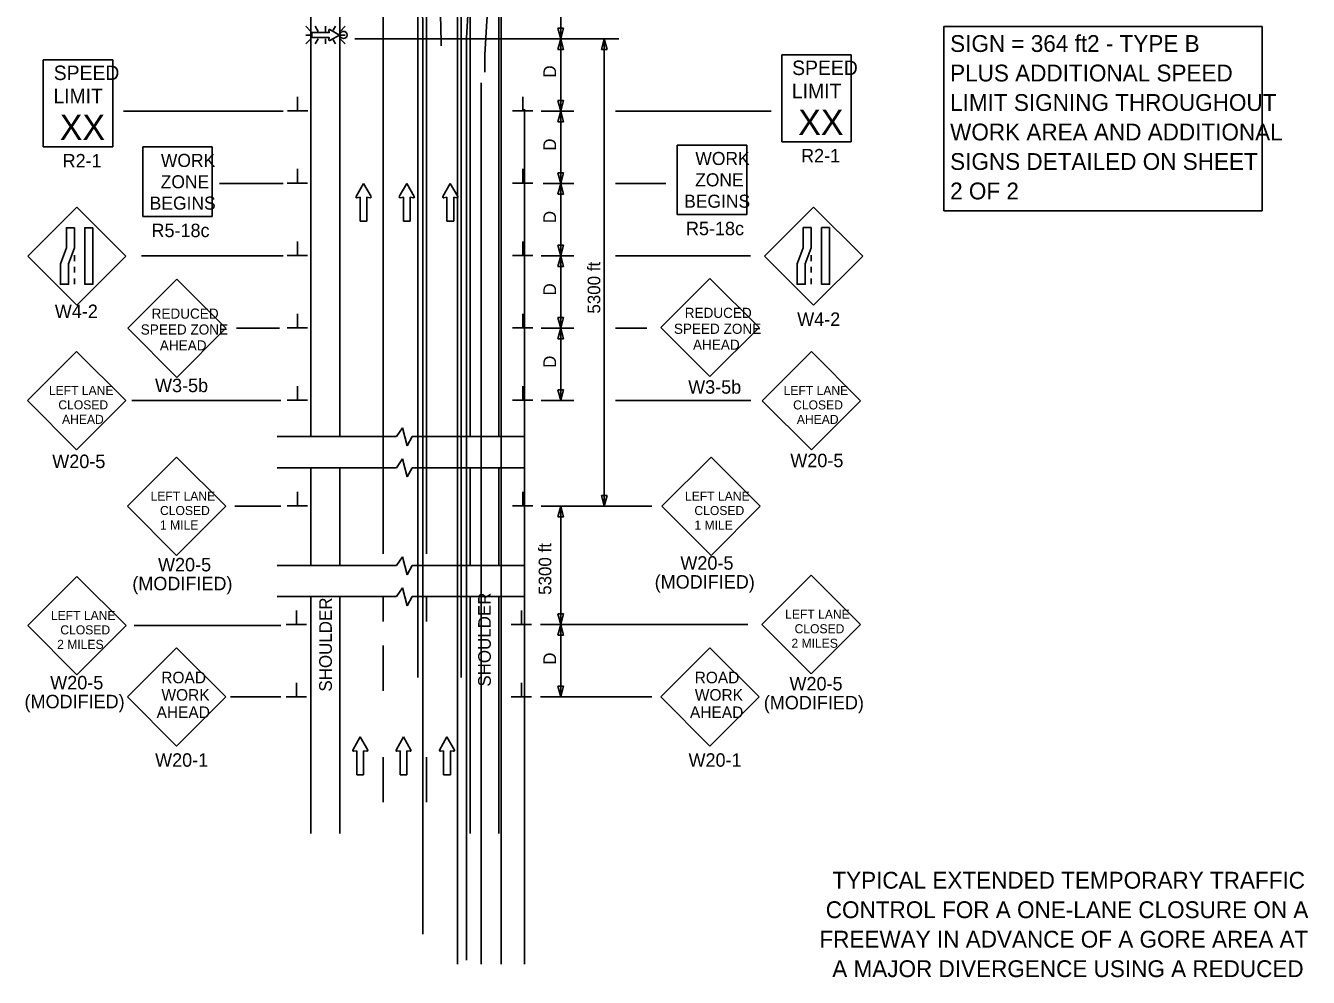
# Model space of a CAD drawing. Extents: x 16284 to 18465, y 5417 to 6974.
# Drawn here: x 16728 to 17436, y 5990 to 6516 of the extents above; entities that cross this region are included whole.
import ezdxf

# ---------------------------------------------------------------- set-up
doc = ezdxf.new("R2010")
doc.units = 0
for name, color, linetype in [('ALI_LEGAL_EX', 7, 'Continuous'), ('BORDER', 7, 'Continuous'), ('MT_SCRATCH_LEVEL_E', 7, 'Continuous'), ('PAVT_EDGE_EX', 7, 'Continuous'), ('TRAFFIC_SIGNS_PR', 7, 'Continuous'), ('TYPICAL_TEXT_DIMEN_EX', 7, 'Continuous'), ('TYPICAL_TEXT_DIMEN_PR', 7, 'Continuous')]:
    doc.layers.add(name, color=color, linetype=linetype)

msp = doc.modelspace()

# ---------------------------------------------------------------- linework, layer by layer
at = {"layer": 'ALI_LEGAL_EX'}
for p, q in [((16944.3, 6974.12), (16944.3, 6155.98)), ((16968.3, 6974.12), (16968.3, 6155.98)), ((16966.29, 6836.53), (16966.29, 5997.6)), ((16990.29, 6836.53), (16990.29, 5997.6)), ((16925.13, 6287.02), (16925.13, 6564.7)), ((16949.13, 6287.02), (16949.13, 6564.7)), ((16947.12, 6014.17), (16947.12, 6514.52)), ((16971.12, 5999.68), (16971.12, 6500.03)), ((16979.26, 5997.6), (16979.26, 6484.64)), ((17003.26, 5997.6), (17003.26, 6470.15)), ((16925.13, 6301.47), (16925.13, 6224.31)), ((16949.13, 6301.47), (16949.13, 6224.31))]:
    msp.add_line(p, q, dxfattribs=at)
for points in [[(16925.13, 6487.02), (16925.13, 6509.03)], [(16949.13, 6487.02), (16949.13, 6509.03)], [(16925.13, 6387.02), (16925.13, 6412.02)], [(16949.13, 6387.02), (16949.13, 6412.02)], [(16925.13, 6312.02), (16925.13, 6287.02)], [(16925.13, 6312.02), (16925.13, 6289.11)], [(16949.13, 6289.11), (16949.13, 6312.02)], [(16925.13, 6273.62), (16925.13, 6248.62)], [(16925.13, 6200.69), (16925.13, 6187.02)], [(16949.13, 6187.02), (16949.13, 6200.69)], [(16925.13, 6173.62), (16925.13, 6148.62)], [(16925.13, 6112.02), (16925.13, 6087.02)], [(16949.13, 6087.02), (16949.13, 6112.02)]]:
    msp.add_lwpolyline(points, dxfattribs=at)
for centre, radius, start, end in [((16583.12, 6514.52), 364, 0, 57.29578), ((16593.27, 6505.1), 364, 0, 57.29578), ((17311.12, 6500.03), 340, 129.56655, 180), ((17321.27, 6490.61), 340, 129.56655, 180)]:
    msp.add_arc(centre, radius, start, end, dxfattribs=at)
at = {"layer": 'MT_SCRATCH_LEVEL_E'}
for p, q in [((16914.27, 6429.09), (16910.15, 6421.85)), ((16918.41, 6421.85), (16914.27, 6429.09)), ((16938.17, 6429.09), (16934.06, 6421.85)), ((16942.32, 6421.85), (16938.17, 6429.09)), ((16962.22, 6429.09), (16958.11, 6421.85)), ((16966.37, 6421.85), (16962.22, 6429.09)), ((16910.64, 6421.16), (16912.41, 6421.48)), ((16912.41, 6421.48), (16912.41, 6408.22)), ((16916.16, 6408.22), (16916.16, 6421.48)), ((16916.16, 6421.48), (16917.93, 6421.16)), ((16934.54, 6421.16), (16936.32, 6421.48)), ((16936.32, 6421.48), (16936.32, 6408.22)), ((16940.06, 6408.22), (16940.06, 6421.48)), ((16940.06, 6421.48), (16941.84, 6421.16)), ((16958.59, 6421.16), (16960.37, 6421.48)), ((16960.37, 6421.48), (16960.37, 6408.22)), ((16964.11, 6408.22), (16964.11, 6421.48)), ((16964.11, 6421.48), (16965.89, 6421.16)), ((16912.41, 6408.22), (16916.16, 6408.22)), ((16936.32, 6408.22), (16940.06, 6408.22)), ((16960.37, 6408.22), (16964.11, 6408.22)), ((16912.44, 6123.16), (16908.32, 6115.92)), ((16916.58, 6115.92), (16912.44, 6123.16)), ((16936.34, 6123.16), (16932.23, 6115.92)), ((16940.49, 6115.92), (16936.34, 6123.16)), ((16960.39, 6123.16), (16956.28, 6115.92)), ((16964.54, 6115.92), (16960.39, 6123.16)), ((16908.81, 6115.24), (16910.58, 6115.55)), ((16910.58, 6115.55), (16910.58, 6102.29)), ((16914.33, 6102.29), (16914.33, 6115.55)), ((16914.33, 6115.55), (16916.1, 6115.24)), ((16932.71, 6115.24), (16934.49, 6115.55)), ((16934.49, 6115.55), (16934.49, 6102.29)), ((16938.23, 6102.29), (16938.23, 6115.55)), ((16938.23, 6115.55), (16940.01, 6115.24)), ((16956.76, 6115.24), (16958.54, 6115.55)), ((16958.54, 6115.55), (16958.54, 6102.29)), ((16962.28, 6102.29), (16962.28, 6115.55)), ((16962.28, 6115.55), (16964.06, 6115.24)), ((16910.58, 6102.29), (16914.33, 6102.29)), ((16934.49, 6102.29), (16938.23, 6102.29)), ((16958.54, 6102.29), (16962.28, 6102.29))]:
    msp.add_line(p, q, dxfattribs=at)
for centre, start, end in [((16910.56, 6421.62), 150.42484, 279.96381), ((16918, 6421.62), 260.03619, 29.77312), ((16934.47, 6421.62), 150.42484, 279.96381), ((16941.91, 6421.62), 260.03619, 29.77312), ((16958.52, 6421.62), 150.42484, 279.96381), ((16965.96, 6421.62), 260.03619, 29.77312), ((16908.73, 6115.69), 150.42484, 279.96381), ((16916.17, 6115.7), 260.03619, 29.77312), ((16932.64, 6115.69), 150.42484, 279.96381), ((16940.08, 6115.7), 260.03619, 29.77312), ((16956.69, 6115.69), 150.42484, 279.96381), ((16964.13, 6115.7), 260.03619, 29.77312)]:
    msp.add_arc(centre, 0.463, start, end, dxfattribs=at)
at = {"layer": 'PAVT_EDGE_EX'}
for p, q in [((16885.13, 6564.7), (16885.13, 6289.11)), ((16901.13, 6564.7), (16901.13, 6289.11)), ((16973.13, 6564.7), (16973.13, 6289.11)), ((16989.13, 6564.7), (16989.13, 6289.11)), ((16885.13, 6271.97), (16885.13, 6217.82)), ((16901.13, 6271.97), (16901.13, 6217.82)), ((16973.13, 6271.97), (16973.13, 6217.82)), ((16989.13, 6271.97), (16989.13, 6217.82)), ((16885.13, 6200.69), (16885.13, 6069.75)), ((16901.13, 6200.69), (16901.13, 6069.75)), ((16973.13, 6200.69), (16973.13, 6069.75)), ((16989.13, 6200.69), (16989.13, 6069.75))]:
    msp.add_line(p, q, dxfattribs=at)
at = {"layer": 'TRAFFIC_SIGNS_PR'}
for p, q in [((16885.2, 6513.11), (16882.38, 6515.93)), ((16887.5, 6515.93), (16889.13, 6513.11)), ((16893.29, 6513.11), (16893.29, 6515.93)), ((16898.76, 6515.93), (16897.55, 6513.83)), ((16904.19, 6515.92), (16901.37, 6513.11)), ((16885.2, 6511.07), (16882.38, 6511.07)), ((16885.2, 6509.04), (16882.38, 6506.22)), ((16889.15, 6509.04), (16887.52, 6506.22)), ((16893.29, 6509.04), (16893.29, 6506.22)), ((16897.47, 6508.41), (16898.73, 6506.22)), ((16901.37, 6511.07), (16904.19, 6511.07)), ((16904.19, 6506.22), (16901.37, 6509.04)), ((16737.29, 6497.33), (16775.69, 6497.33)), ((16737.29, 6449.33), (16737.29, 6497.33)), ((16775.69, 6449.33), (16775.69, 6497.33)), ((17145.4, 6500.11), (17183.8, 6500.11)), ((17145.4, 6452.11), (17145.4, 6500.11)), ((17183.8, 6452.11), (17183.8, 6500.11)), ((17145.4, 6452.11), (17183.8, 6452.11)), ((16737.29, 6449.33), (16775.69, 6449.33)), ((16792.29, 6410.82), (16792.29, 6449.22)), ((16792.29, 6449.22), (16830.69, 6449.22)), ((16830.69, 6410.82), (16830.69, 6449.22)), ((17087.66, 6411.89), (17087.66, 6450.29)), ((17087.66, 6450.29), (17126.06, 6450.29)), ((17126.06, 6411.89), (17126.06, 6450.29)), ((16755.84, 6416.02), (16728.69, 6388.86)), ((16782.99, 6388.86), (16755.84, 6416.02)), ((17163, 6416.04), (17135.85, 6388.89)), ((17190.15, 6388.89), (17163, 6416.04)), ((16792.29, 6410.82), (16830.69, 6410.82)), ((17087.66, 6411.89), (17126.06, 6411.89)), ((16728.69, 6388.86), (16755.84, 6361.71)), ((16754.59, 6389.36), (16754.59, 6386.16)), ((16755.84, 6361.71), (16782.99, 6388.86)), ((17135.85, 6388.89), (17163, 6361.73)), ((17161.75, 6389.38), (17161.75, 6386.18)), ((17163, 6361.73), (17190.15, 6388.89)), ((16754.59, 6382.96), (16754.59, 6379.76)), ((17161.75, 6382.98), (17161.75, 6379.78)), ((16754.59, 6376.56), (16754.59, 6373.36)), ((16811.09, 6376.17), (16783.94, 6349.02)), ((16838.25, 6349.02), (16811.09, 6376.17)), ((17105.74, 6376.58), (17078.59, 6349.43)), ((17132.9, 6349.43), (17105.74, 6376.58)), ((17161.75, 6376.58), (17161.75, 6373.38)), ((16783.94, 6349.02), (16811.09, 6321.87)), ((16811.09, 6321.87), (16838.25, 6349.02)), ((17078.59, 6349.43), (17105.74, 6322.27)), ((17105.74, 6322.27), (17132.9, 6349.43)), ((16755.68, 6336.22), (16728.49, 6309.03)), ((16782.86, 6309.03), (16755.68, 6336.22)), ((17161.77, 6336.19), (17134.58, 6309)), ((17188.95, 6309), (17161.77, 6336.19)), ((16728.49, 6309.03), (16755.68, 6281.85)), ((16755.68, 6281.85), (16782.86, 6309.03)), ((17134.58, 6309), (17161.77, 6281.81)), ((17161.77, 6281.81), (17188.95, 6309)), ((16810.96, 6277.82), (16783.77, 6250.64)), ((16838.15, 6250.64), (16810.96, 6277.82)), ((17106.33, 6277.81), (17079.14, 6250.62)), ((17133.51, 6250.62), (17106.33, 6277.81)), ((16783.77, 6250.64), (16810.96, 6223.45)), ((16810.96, 6223.45), (16838.15, 6250.64)), ((17079.14, 6250.62), (17106.33, 6223.43)), ((17106.33, 6223.43), (17133.51, 6250.62)), ((16755.88, 6211.86), (16728.69, 6184.67)), ((16783.07, 6184.67), (16755.88, 6211.86)), ((17161.68, 6212.48), (17134.49, 6185.29)), ((17188.86, 6185.29), (17161.68, 6212.48)), ((16728.69, 6184.67), (16755.88, 6157.49)), ((16755.88, 6157.49), (16783.07, 6184.67)), ((17134.49, 6185.29), (17161.68, 6158.11)), ((17161.68, 6158.11), (17188.86, 6185.29)), ((16810.94, 6172.41), (16783.79, 6145.26)), ((16838.09, 6145.26), (16810.94, 6172.41)), ((17105.72, 6172.41), (17078.56, 6145.26)), ((17132.87, 6145.26), (17105.72, 6172.41)), ((16783.79, 6145.26), (16810.94, 6118.11)), ((16810.94, 6118.11), (16838.09, 6145.26)), ((17078.56, 6145.26), (17105.72, 6118.11)), ((17105.72, 6118.11), (17132.87, 6145.26))]:
    msp.add_line(p, q, dxfattribs=at)
for points in [[(16895.11, 6513.76), (16895.34, 6512.46), (16885.62, 6512.46), (16885.62, 6509.72), (16895.34, 6509.72), (16895.11, 6508.41)], [(16895.61, 6508.06), (16900.92, 6511.07), (16895.61, 6514.11)]]:
    msp.add_lwpolyline(points, dxfattribs=at)
for points in [[(16754.59, 6404.6), (16754.59, 6393.42), (16751.25, 6384.54), (16751.25, 6373.36), (16746.75, 6373.36), (16746.75, 6384.54), (16750.1, 6393.42), (16750.1, 6404.6)], [(16764.73, 6404.6), (16764.73, 6373.36), (16760.23, 6373.36), (16760.23, 6404.6)], [(17161.75, 6404.62), (17161.75, 6393.44), (17158.41, 6384.56), (17158.41, 6373.38), (17153.91, 6373.38), (17153.91, 6384.56), (17157.26, 6393.44), (17157.26, 6404.62)], [(17171.89, 6404.62), (17171.89, 6373.38), (17167.4, 6373.38), (17167.4, 6404.62)]]:
    msp.add_lwpolyline(points, close=True, dxfattribs=at)
msp.add_circle((16903.24, 6511.12), 2, dxfattribs=at)
for centre, start, end in [((16895.45, 6513.81), 61.48329, 189.95933), ((16895.45, 6508.36), 170.73078, 298.89165)]:
    msp.add_arc(centre, 0.341, start, end, dxfattribs=at)
at = {"layer": 'TYPICAL_TEXT_DIMEN_EX'}
msp.add_lwpolyline([(17235.07, 6515.73), (17410.86, 6515.73), (17410.86, 6414), (17235.07, 6414)], close=True, dxfattribs=at)
at = {"layer": 'TYPICAL_TEXT_DIMEN_PR'}
for p, q in [((17023.24, 6541.14), (17023.24, 6509.03)), ((17023.24, 6509.03), (17021.67, 6514.9)), ((17021.67, 6514.9), (17023.24, 6514.9)), ((17023.24, 6514.9), (17024.81, 6514.9)), ((17024.81, 6514.9), (17023.24, 6509.03)), ((16909.53, 6509.03), (17055.35, 6509.03)), ((17021.67, 6503.17), (17023.24, 6509.03)), ((17023.24, 6509.03), (17023.24, 6469.03)), ((17023.24, 6509.03), (17024.81, 6503.17)), ((17045.77, 6503.17), (17047.34, 6509.03)), ((17047.34, 6509.03), (17047.34, 6250.63)), ((17047.34, 6509.03), (17048.91, 6503.17)), ((17023.24, 6503.17), (17021.67, 6503.17)), ((17024.81, 6503.17), (17023.24, 6503.17)), ((17047.34, 6503.17), (17045.77, 6503.17)), ((17048.91, 6503.17), (17047.34, 6503.17)), ((16877.81, 6469.12), (16877.81, 6476.9)), ((17002.26, 6469.12), (17002.26, 6476.9)), ((17023.24, 6469.03), (17021.67, 6474.9)), ((17021.67, 6474.9), (17023.24, 6474.9)), ((17023.24, 6474.9), (17024.81, 6474.9)), ((17024.81, 6474.9), (17023.24, 6469.03)), ((16869.89, 6469.03), (16781.59, 6469.03)), ((16883.43, 6469.12), (16872.18, 6469.12)), ((17007.88, 6469.12), (16996.63, 6469.12)), ((17030.45, 6469.03), (17012.41, 6469.03)), ((17021.67, 6463.17), (17023.24, 6469.03)), ((17023.24, 6469.03), (17023.24, 6429.03)), ((17023.24, 6469.03), (17024.81, 6463.17)), ((17139.57, 6469.03), (17053.57, 6469.03)), ((17023.24, 6463.17), (17021.67, 6463.17)), ((17024.81, 6463.17), (17023.24, 6463.17)), ((16877.69, 6429.28), (16877.69, 6437.06)), ((17002.26, 6429.28), (17002.26, 6437.06)), ((17023.24, 6429.03), (17021.67, 6434.9)), ((17021.67, 6434.9), (17023.24, 6434.9)), ((17023.24, 6434.9), (17024.81, 6434.9)), ((17024.81, 6434.9), (17023.24, 6429.03)), ((16869.89, 6429.03), (16834.72, 6429.03)), ((16883.32, 6429.28), (16872.07, 6429.28)), ((17007.88, 6429.28), (16996.63, 6429.28)), ((17030.45, 6429.03), (17013.53, 6429.03)), ((17021.67, 6423.17), (17023.24, 6429.03)), ((17023.24, 6423.17), (17021.67, 6423.17)), ((17023.24, 6429.03), (17023.24, 6389.03)), ((17023.24, 6429.03), (17024.81, 6423.17)), ((17024.81, 6423.17), (17023.24, 6423.17)), ((17081.26, 6429.03), (17053.57, 6429.03)), ((16877.69, 6389.28), (16877.69, 6397.06)), ((17002.26, 6389.28), (17002.26, 6397.06)), ((17023.24, 6389.03), (17021.67, 6394.9)), ((17021.67, 6394.9), (17023.24, 6394.9)), ((17023.24, 6394.9), (17024.81, 6394.9)), ((17024.81, 6394.9), (17023.24, 6389.03)), ((16869.89, 6389.03), (16791.54, 6389.03)), ((16883.32, 6389.28), (16872.07, 6389.28)), ((17007.88, 6389.28), (16996.63, 6389.28)), ((17030.45, 6389.03), (17012.41, 6389.03)), ((17021.67, 6383.17), (17023.24, 6389.03)), ((17023.24, 6389.03), (17023.24, 6349.03)), ((17023.24, 6389.03), (17024.81, 6383.17)), ((17128.19, 6389.03), (17053.57, 6389.03)), ((17023.24, 6383.17), (17021.67, 6383.17)), ((17024.81, 6383.17), (17023.24, 6383.17)), ((16877.69, 6349.28), (16877.69, 6357.06)), ((17002.26, 6349.28), (17002.26, 6357.06)), ((17023.24, 6349.03), (17021.67, 6354.9)), ((17021.67, 6354.9), (17023.24, 6354.9)), ((17023.24, 6354.9), (17024.81, 6354.9)), ((17024.81, 6354.9), (17023.24, 6349.03)), ((16867.76, 6349.03), (16844.09, 6349.03)), ((16883.32, 6349.28), (16872.07, 6349.28)), ((17007.88, 6349.28), (16996.63, 6349.28)), ((17030.45, 6349.03), (17012.41, 6349.03)), ((17021.67, 6343.17), (17023.24, 6349.03)), ((17023.24, 6349.03), (17023.24, 6309.03)), ((17023.24, 6349.03), (17024.81, 6343.17)), ((17070.76, 6349.03), (17053.57, 6349.03)), ((17023.24, 6343.17), (17021.67, 6343.17)), ((17024.81, 6343.17), (17023.24, 6343.17)), ((16877.69, 6309.28), (16877.69, 6317.06)), ((17002.26, 6309.28), (17002.26, 6317.06)), ((16883.32, 6309.28), (16872.07, 6309.28)), ((17007.88, 6309.28), (16996.63, 6309.28)), ((17023.24, 6309.03), (17021.67, 6314.9)), ((17021.67, 6314.9), (17023.24, 6314.9)), ((17023.24, 6314.9), (17024.81, 6314.9)), ((17024.81, 6314.9), (17023.24, 6309.03)), ((16868.54, 6309.03), (16786.22, 6309.03)), ((17030.45, 6309.03), (17012.41, 6309.03)), ((17128.33, 6309.03), (17053.57, 6309.03)), ((16932.48, 6289.11), (16866.54, 6289.11)), ((16935.74, 6293.91), (16932.48, 6289.11)), ((16938.48, 6283.97), (16935.74, 6293.91)), ((16941.22, 6289.11), (16938.48, 6283.97)), ((17003.55, 6289.11), (16941.22, 6289.11)), ((16935.74, 6276.77), (16932.48, 6271.97)), ((16938.48, 6266.83), (16935.74, 6276.77)), ((16932.48, 6271.97), (16866.54, 6271.97)), ((16941.22, 6271.97), (16938.48, 6266.83)), ((17003.55, 6271.97), (16941.22, 6271.97)), ((16877.69, 6250.88), (16877.69, 6258.66)), ((17002.26, 6250.88), (17002.26, 6258.66)), ((17047.34, 6250.63), (17045.77, 6256.5)), ((17045.77, 6256.5), (17047.34, 6256.5)), ((17047.34, 6256.5), (17048.91, 6256.5)), ((17048.91, 6256.5), (17047.34, 6250.63)), ((16868.54, 6250.63), (16843.07, 6250.63)), ((16883.32, 6250.88), (16872.07, 6250.88)), ((17007.88, 6250.88), (16996.63, 6250.88)), ((17073.6, 6250.63), (17012.41, 6250.63)), ((17021.67, 6244.77), (17023.24, 6250.63)), ((17023.24, 6250.63), (17023.24, 6185.29)), ((17023.24, 6250.63), (17024.81, 6244.77)), ((17023.24, 6244.77), (17021.67, 6244.77)), ((17024.81, 6244.77), (17023.24, 6244.77)), ((16932.48, 6217.82), (16866.54, 6217.82)), ((16935.74, 6222.62), (16932.48, 6217.82)), ((16938.48, 6212.69), (16935.74, 6222.62)), ((16941.22, 6217.82), (16938.48, 6212.69)), ((17003.55, 6217.82), (16941.22, 6217.82)), ((16935.74, 6205.49), (16932.48, 6200.69)), ((16938.48, 6195.55), (16935.74, 6205.49)), ((16932.48, 6200.69), (16866.54, 6200.69)), ((16941.22, 6200.69), (16938.48, 6195.55)), ((17003.55, 6200.69), (16941.22, 6200.69)), ((16877.14, 6185.29), (16877.14, 6193.08)), ((17001.51, 6185.29), (17001.51, 6193.08)), ((17023.24, 6185.29), (17021.67, 6191.16)), ((17021.67, 6191.16), (17023.24, 6191.16)), ((17023.24, 6191.16), (17024.81, 6191.16)), ((17024.81, 6191.16), (17023.24, 6185.29)), ((16868.54, 6184.67), (16787.47, 6184.67)), ((16882.76, 6185.29), (16871.51, 6185.29)), ((17007.13, 6185.29), (16995.88, 6185.29)), ((17126.67, 6185.29), (17012.13, 6185.29)), ((17021.67, 6179.43), (17023.24, 6185.29)), ((17023.24, 6185.29), (17023.24, 6145.29)), ((17023.24, 6185.29), (17024.81, 6179.43)), ((17023.24, 6179.43), (17021.67, 6179.43)), ((17024.81, 6179.43), (17023.24, 6179.43)), ((16877.14, 6145.29), (16877.14, 6153.08)), ((17001.51, 6145.29), (17001.51, 6153.08)), ((17023.24, 6145.29), (17021.67, 6151.16)), ((17021.67, 6151.16), (17023.24, 6151.16)), ((17023.24, 6151.16), (17024.81, 6151.16)), ((17024.81, 6151.16), (17023.24, 6145.29)), ((16868.54, 6145.29), (16840.68, 6145.29)), ((16882.76, 6145.29), (16871.51, 6145.29)), ((17007.13, 6145.29), (16995.88, 6145.29)), ((17073.6, 6145.29), (17012.13, 6145.29))]:
    msp.add_line(p, q, dxfattribs=at)

# ---------------------------------------------------------------- texts
at = {"layer": 'BORDER'}
for s, p in [('TYPICAL EXTENDED TEMPORARY TRAFFIC', (17173.37, 6039.3)), ('CONTROL FOR A ONE-LANE CLOSURE ON A', (17169.74, 6023)), ('FREEWAY IN ADVANCE OF A GORE AREA AT', (17166.24, 6006.7)), ('A MAJOR DIVERGENCE USING A REDUCED', (17173.34, 5990.4))]:
    msp.add_text(s, height=9.3, dxfattribs=at).set_placement(p)
at = {"layer": 'TRAFFIC_SIGNS_PR'}
for s, height, p in [('SPEED', 8, (16743.06, 6486.2)), ('SPEED', 8, (17151.17, 6488.98)), ('LIMIT', 8, (16742.9, 6473.4)), ('LIMIT', 8, (17151, 6476.18)), ('XX', 14.031, (16746.4, 6453.09)), ('XX', 14.031, (17154.51, 6455.87)), ('R2-1', 7.44, (16747.97, 6437.9)), ('WORK', 7.217, (16802.29, 6438.19)), ('WORK', 7.217, (17097.67, 6439.26)), ('R2-1', 7.44, (17156.08, 6440.67)), ('ZONE', 7.217, (16802.17, 6426.38)), ('ZONE', 7.217, (17097.55, 6427.45)), ('BEGINS', 7.217, (17091.48, 6415.64)), ('BEGINS', 7.217, (16796.1, 6414.57)), ('R5-18c', 7.44, (16797.1, 6399.38)), ('R5-18c', 7.44, (17092.48, 6400.45)), ('W4-2', 7.44, (16743.67, 6354.67)), ('REDUCED', 5.6, (16797.15, 6354.33)), ('REDUCED', 5.6, (17091.8, 6354.74)), ('W4-2', 7.44, (17153.96, 6350.3)), ('SPEED ZONE', 5.6, (16791.14, 6345.53)), ('SPEED ZONE', 5.6, (17085.8, 6345.94)), ('AHEAD', 5.6, (16801.7, 6336.73)), ('AHEAD', 5.6, (17096.35, 6337.14)), ('LEFT LANE', 5.006, (16740.36, 6312.19)), ('W3-5b', 7.44, (16799.05, 6313.71)), ('W3-5b', 7.44, (17093.7, 6312.86)), ('LEFT LANE', 5.006, (17146.45, 6312.16)), ('CLOSED', 5.006, (16745.6, 6304.19)), ('CLOSED', 5.006, (17151.69, 6304.15)), ('AHEAD', 5.006, (16747.65, 6296.18)), ('AHEAD', 5.006, (17153.74, 6296.14)), ('W20-5', 7.449, (16742.24, 6271.74)), ('W20-5', 7.449, (17150.14, 6272.23)), ('LEFT LANE', 5.006, (16796.57, 6253.79)), ('LEFT LANE', 5.006, (17091.94, 6253.78)), ('CLOSED', 5.006, (16801.79, 6245.78)), ('CLOSED', 5.006, (17097.15, 6245.77)), ('1 MILE', 5.006, (16801.78, 6237.78)), ('1 MILE', 5.006, (17097.15, 6237.76)), ('W20-5', 7.449, (16800.7, 6214.65)), ('W20-5', 7.449, (17089.38, 6215.58)), ('(MODIFIED)', 7.449, (16786.5, 6204.2)), ('(MODIFIED)', 7.449, (17075.18, 6205.13)), ('LEFT LANE', 5.006, (16741.49, 6187.83)), ('LEFT LANE', 5.006, (17147.29, 6188.45)), ('CLOSED', 5.006, (16746.7, 6179.82)), ('CLOSED', 5.006, (17152.5, 6180.44)), ('2 MILES', 5.006, (16744.95, 6171.81)), ('2 MILES', 5.006, (17150.75, 6172.43)), ('W20-5', 7.449, (16741.12, 6149.44)), ('ROAD', 6.4, (16802.48, 6152.79)), ('ROAD', 6.4, (17097.26, 6152.79)), ('W20-5', 7.449, (17149.69, 6148.85)), ('(MODIFIED)', 7.449, (16726.92, 6138.98)), ('WORK', 6.4, (16802.59, 6143.19)), ('WORK', 6.4, (17097.37, 6143.19)), ('(MODIFIED)', 7.449, (17135.49, 6138.4)), ('AHEAD', 6.4, (16799.9, 6133.59)), ('AHEAD', 6.4, (17094.68, 6133.59)), ('W20-1', 7.44, (16799.11, 6106.67)), ('W20-1', 7.44, (17093.89, 6106.67))]:
    msp.add_text(s, height=height, dxfattribs=at).set_placement(p)
at = {"layer": 'TYPICAL_TEXT_DIMEN_EX'}
for s, p in [('SIGN = 364 ft2 - TYPE B', (17238.47, 6501.74)), ('PLUS ADDITIONAL SPEED', (17238.47, 6485.44)), ('LIMIT SIGNING THROUGHOUT', (17238.47, 6469.14)), ('WORK AREA AND ADDITIONAL', (17238.47, 6452.84)), ('SIGNS DETAILED ON SHEET', (17238.47, 6436.54)), ('2 OF 2', (17238.47, 6420.24))]:
    msp.add_text(s, height=9.3, dxfattribs=at).set_placement(p)
at = {"layer": 'TYPICAL_TEXT_DIMEN_PR'}
for s, p in [('D', (17020.68, 6487.55)), ('D', (17020.68, 6447.12)), ('D', (17020.68, 6407.12)), ('5300 ft', (17045.14, 6357.12)), ('D', (17020.68, 6367.12)), ('D', (17020.68, 6327.12)), ('5300 ft', (17018.06, 6201.67)), ('SHOULDER', (16896.77, 6148.2)), ('SHOULDER', (16984.63, 6150.94)), ('D', (17020.68, 6163.04))]:
    msp.add_text(s, height=7, rotation=90, dxfattribs=at).set_placement(p)

doc.saveas('drawing.dxf')
